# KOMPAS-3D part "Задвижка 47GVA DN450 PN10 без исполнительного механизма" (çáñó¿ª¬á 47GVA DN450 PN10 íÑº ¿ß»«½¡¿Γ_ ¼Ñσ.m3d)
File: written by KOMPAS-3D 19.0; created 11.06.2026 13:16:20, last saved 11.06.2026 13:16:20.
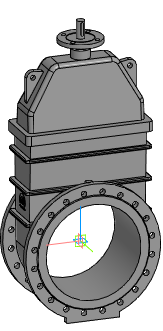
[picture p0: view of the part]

Document properties: Автор: Евгений; Полное имя файла: Z:\3.Личные\kachalov\001_3d для проектировщиков\2.2 Тип 47GVA, 47GVA.Z\_stp\_stp_Задвижка 47GVA DN40-DN1000 без исп.мех\Задвижка 47GVA DN450 PN10 без исполнит_ мех.m3d

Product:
- Part/product: Задвижка 47GVA DN450 PN10 без исполнительного механизма

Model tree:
1. Операция без истории:1  (labels: Задвижка 47GVA DN450 PN10 без исполнительного механизма)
